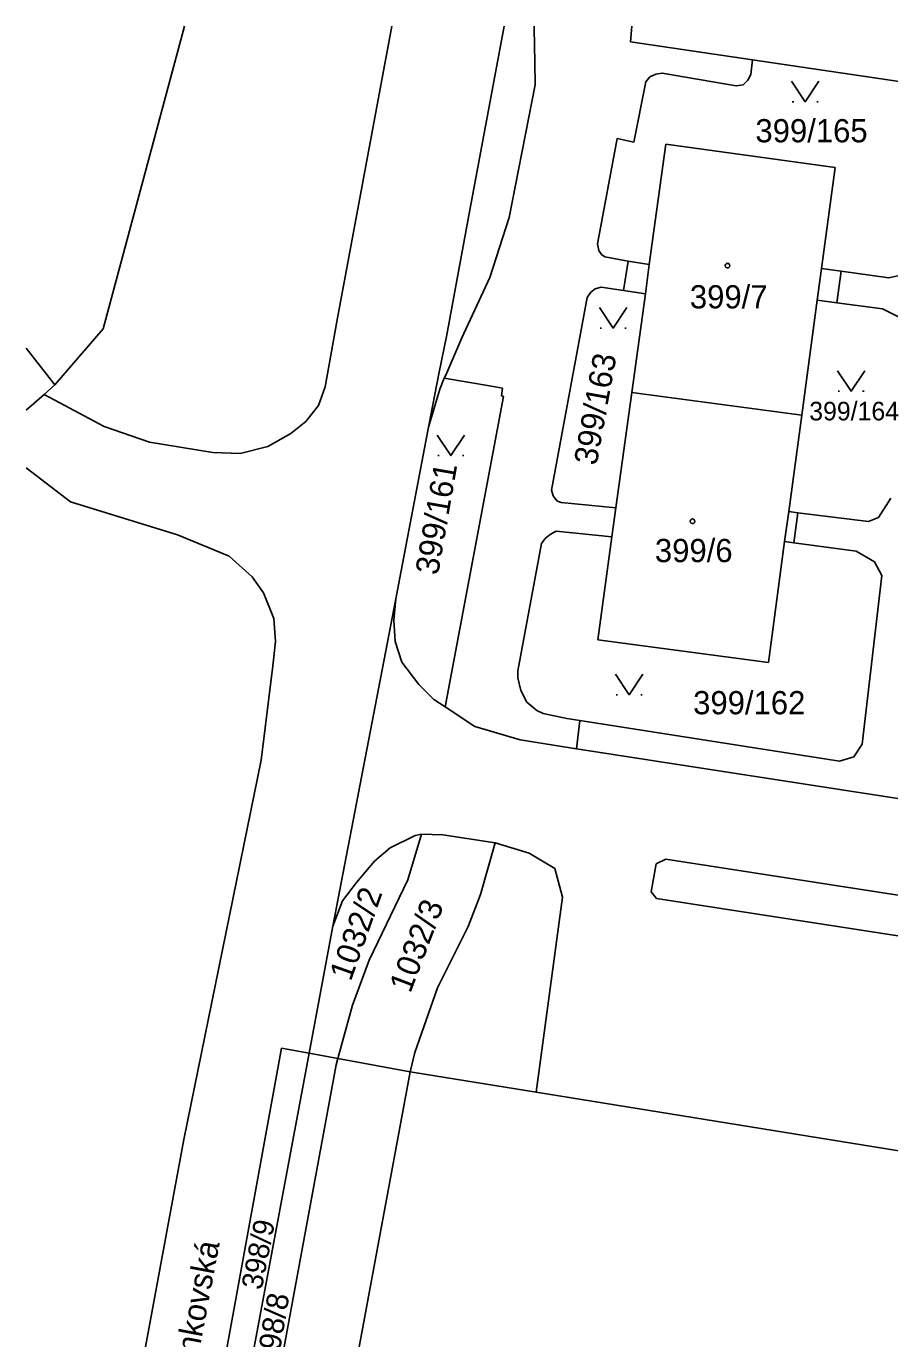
# Model space of a CAD drawing. Extents: x -851495 to -851222, y -1010479 to -1010202.
# Drawn here: x -851494.8 to -851431.6, y -1010299.4 to -1010203.3 of the extents above; entities that cross this region are included whole.
import ezdxf

# ---------------------------------------------------------------- set-up
doc = ezdxf.new("R2010")
doc.units = 0
for name, color, linetype in [('1', 7, 'Continuous'), ('12', 7, 'Continuous'), ('2', 7, 'Continuous'), ('3', 7, 'Continuous'), ('4', 7, 'Continuous'), ('5', 7, 'Continuous'), ('7', 7, 'Continuous')]:
    doc.layers.add(name, color=color, linetype=linetype)

# ---------------------------------------------------------------- blocks, each defined once
blk = doc.blocks.new('314')
for p, q in [((-0.95, 0), (-0.85, 0)), ((0.85, 0), (0.95, 0))]:
    blk.add_line(p, q)
blk.add_lwpolyline([(-1, 1.5), (0, 0), (1, 1.5)])
blk = doc.blocks.new('404')
blk.add_lwpolyline([(0, 0.17), (0.1, 0.15), (0.15, 0.06), (0.17, 0), (0.15, -0.09), (0.07, -0.16), (0, -0.17), (-0.09, -0.14), (-0.15, -0.08), (-0.17, 0), (-0.15, 0.09), (-0.07, 0.16), (0, 0.17)])

msp = doc.modelspace()

# ---------------------------------------------------------------- linework, layer by layer
at = {"layer": '1'}
for p, q in [((-851489.19, -1010225.42), (-851483.22, -1010203.26)), ((-851457.63, -1010203.26), (-851457.62, -1010203.43)), ((-851457.62, -1010203.43), (-851457.56, -1010205.89)), ((-851450.57, -1010204.41), (-851450.46, -1010203.26)), ((-851450.57, -1010204.41), (-851441.63, -1010205.73)), ((-851441.76, -1010206.79), (-851441.63, -1010205.73)), ((-851441.63, -1010205.73), (-851427.84, -1010207.75)), ((-851457.56, -1010205.89), (-851457.54, -1010207.55)), ((-851448.71, -1010206.76), (-851448.24, -1010206.7)), ((-851448.24, -1010206.7), (-851442.84, -1010207.63)), ((-851457.54, -1010207.55), (-851459.44, -1010217.27)), ((-851450.32, -1010211.75), (-851449.44, -1010207.33)), ((-851449.44, -1010207.33), (-851449.15, -1010206.97)), ((-851449.15, -1010206.97), (-851448.71, -1010206.76)), ((-851442.84, -1010207.63), (-851442.31, -1010207.55)), ((-851442.31, -1010207.55), (-851441.98, -1010207.22)), ((-851441.98, -1010207.22), (-851441.76, -1010206.79)), ((-851452.99, -1010219.19), (-851451.54, -1010211.49)), ((-851451.54, -1010211.49), (-851450.32, -1010211.75)), ((-851447.97, -1010211.89), (-851449.19, -1010220.71)), ((-851435.58, -1010213.6), (-851447.97, -1010211.89)), ((-851436.57, -1010221), (-851435.58, -1010213.6)), ((-851459.44, -1010217.27), (-851460.87, -1010221.65)), ((-851452.88, -1010219.67), (-851452.99, -1010219.19)), ((-851452.68, -1010219.97), (-851452.88, -1010219.67)), ((-851452.45, -1010220.15), (-851452.68, -1010219.97)), ((-851452.45, -1010220.15), (-851450.73, -1010220.45)), ((-851450.73, -1010220.45), (-851451.07, -1010222.6)), ((-851450.73, -1010220.45), (-851449.19, -1010220.71)), ((-851435.15, -1010221.2), (-851436.57, -1010221)), ((-851460.87, -1010221.65), (-851462.92, -1010226.07)), ((-851435.47, -1010223.51), (-851435.15, -1010221.2)), ((-851435.15, -1010221.2), (-851431.65, -1010221.67)), ((-851431.65, -1010221.67), (-851430.11, -1010221.35)), ((-851453.73, -1010223.13), (-851453.46, -1010222.72)), ((-851453.46, -1010222.72), (-851453.16, -1010222.48)), ((-851453.16, -1010222.48), (-851452.71, -1010222.36)), ((-851452.71, -1010222.36), (-851451.07, -1010222.6)), ((-851451.07, -1010222.6), (-851449.48, -1010222.86)), ((-851450.47, -1010230.07), (-851449.48, -1010222.86)), ((-851456.36, -1010237.22), (-851453.73, -1010223.13)), ((-851436.89, -1010223.32), (-851438.03, -1010231.74)), ((-851435.47, -1010223.51), (-851436.89, -1010223.32)), ((-851432.12, -1010223.96), (-851435.47, -1010223.51)), ((-851430.8, -1010224.61), (-851432.12, -1010223.96)), ((-851492.72, -1010229.51), (-851489.19, -1010225.42)), ((-851492.72, -1010229.51), (-851494.81, -1010226.82)), ((-851462.92, -1010226.07), (-851464.1, -1010228.8)), ((-851464.1, -1010228.8), (-851464.2, -1010229.02)), ((-851493.51, -1010230.22), (-851492.72, -1010229.51)), ((-851464.2, -1010229.02), (-851464.52, -1010229.84)), ((-851464.2, -1010229.02), (-851460.75, -1010229.61)), ((-851460.75, -1010229.61), (-851459.94, -1010229.75)), ((-851459.94, -1010229.75), (-851460.01, -1010230.32)), ((-851494.81, -1010231.37), (-851493.51, -1010230.22)), ((-851464.52, -1010229.84), (-851465.35, -1010232.61)), ((-851459.87, -1010230.36), (-851460.62, -1010234.41)), ((-851460.01, -1010230.32), (-851459.87, -1010230.36)), ((-851451.64, -1010238.53), (-851450.47, -1010230.07)), ((-851438.03, -1010231.74), (-851450.47, -1010230.07)), ((-851467.76, -1010245.18), (-851465.35, -1010232.61)), ((-851438.03, -1010231.74), (-851438.98, -1010238.79)), ((-851460.62, -1010234.41), (-851464.13, -1010253.1)), ((-851456.22, -1010237.65), (-851456.36, -1010237.22)), ((-851455.96, -1010238.02), (-851456.22, -1010237.65)), ((-851455.64, -1010238.14), (-851455.96, -1010238.02)), ((-851455.64, -1010238.14), (-851451.64, -1010238.53)), ((-851432.4, -1010239.22), (-851431.5, -1010237.81)), ((-851451.64, -1010238.53), (-851451.93, -1010240.64)), ((-851438.31, -1010238.88), (-851438.98, -1010238.79)), ((-851438.62, -1010241.08), (-851438.31, -1010238.88)), ((-851438.31, -1010238.88), (-851433.14, -1010239.53)), ((-851433.14, -1010239.53), (-851432.4, -1010239.22)), ((-851456.45, -1010240.47), (-851456.02, -1010240.22)), ((-851451.93, -1010240.64), (-851456.02, -1010240.22)), ((-851458.82, -1010250.47), (-851457.09, -1010241.14)), ((-851457.09, -1010241.14), (-851456.81, -1010240.77)), ((-851456.81, -1010240.77), (-851456.45, -1010240.47)), ((-851451.93, -1010240.64), (-851452.97, -1010248.19)), ((-851440.47, -1010249.84), (-851439.28, -1010241)), ((-851438.62, -1010241.08), (-851439.28, -1010241)), ((-851434.05, -1010241.7), (-851438.62, -1010241.08)), ((-851432.7, -1010242.48), (-851434.05, -1010241.7)), ((-851432.16, -1010243.47), (-851432.7, -1010242.48)), ((-851433.6, -1010255.82), (-851432.16, -1010243.47)), ((-851467.76, -1010245.18), (-851472.37, -1010269.15)), ((-851467.76, -1010245.18), (-851467.89, -1010246.74)), ((-851467.89, -1010246.74), (-851467.81, -1010248.3)), ((-851467.81, -1010248.3), (-851467.31, -1010249.82)), ((-851452.97, -1010248.19), (-851440.47, -1010249.84)), ((-851467.31, -1010249.82), (-851466.07, -1010251.45)), ((-851458.82, -1010250.97), (-851458.82, -1010250.47)), ((-851466.07, -1010251.45), (-851464.96, -1010252.55)), ((-851458.6, -1010251.9), (-851458.82, -1010250.97)), ((-851458.15, -1010252.76), (-851458.6, -1010251.9)), ((-851464.13, -1010253.1), (-851464.96, -1010252.55)), ((-851457.42, -1010253.37), (-851458.15, -1010252.76)), ((-851461.97, -1010254.53), (-851464.13, -1010253.1)), ((-851456.95, -1010253.58), (-851457.42, -1010253.37)), ((-851455.24, -1010253.94), (-851456.95, -1010253.58)), ((-851458.64, -1010255.52), (-851461.97, -1010254.53)), ((-851455.24, -1010253.94), (-851454.28, -1010254.09)), ((-851454.53, -1010256.16), (-851454.28, -1010254.09)), ((-851454.28, -1010254.09), (-851435.27, -1010257.08)), ((-851454.53, -1010256.16), (-851458.64, -1010255.52)), ((-851428.27, -1010260.23), (-851454.53, -1010256.16)), ((-851434.21, -1010256.75), (-851433.6, -1010255.82)), ((-851435.27, -1010257.08), (-851434.21, -1010256.75)), ((-851466.86, -1010265.76), (-851465.87, -1010262.43)), ((-851466.33, -1010262.51), (-851465.87, -1010262.43)), ((-851465.87, -1010262.43), (-851464.32, -1010262.46)), ((-851464.32, -1010262.46), (-851460.48, -1010263.06)), ((-851469.3, -1010264.39), (-851468.17, -1010263.42)), ((-851468.17, -1010263.42), (-851466.33, -1010262.51)), ((-851460.48, -1010263.06), (-851461.55, -1010266.83)), ((-851470.62, -1010265.96), (-851469.3, -1010264.39)), ((-851471.65, -1010267.31), (-851470.62, -1010265.96)), ((-851469.69, -1010271.64), (-851466.86, -1010265.76)), ((-851461.55, -1010266.83), (-851462.45, -1010269.19)), ((-851472.37, -1010269.15), (-851471.65, -1010267.31)), ((-851472.37, -1010269.15), (-851474.1, -1010278.46)), ((-851462.45, -1010269.19), (-851464.7, -1010273.68)), ((-851470.92, -1010274.93), (-851469.69, -1010271.64)), ((-851464.7, -1010273.68), (-851466.35, -1010278.41)), ((-851471.99, -1010278.84), (-851470.92, -1010274.93)), ((-851476.12, -1010278.09), (-851482.49, -1010313.06)), ((-851478.85, -1010303.92), (-851474.1, -1010278.46)), ((-851476.12, -1010278.09), (-851474.1, -1010278.46)), ((-851474.1, -1010278.46), (-851471.99, -1010278.84)), ((-851466.35, -1010278.41), (-851466.71, -1010279.81)), ((-851472.11, -1010279.3), (-851479.01, -1010316.73)), ((-851471.99, -1010278.84), (-851472.11, -1010279.3)), ((-851471.99, -1010278.84), (-851466.71, -1010279.81)), ((-851473.7, -1010317.66), (-851466.71, -1010279.81)), ((-851466.71, -1010279.81), (-851465.64, -1010280)), ((-851465.64, -1010280), (-851457.47, -1010281.32)), ((-851457.47, -1010281.32), (-851386.12, -1010292.85))]:
    msp.add_line(p, q, dxfattribs=at)
at = {"layer": '12'}
for p, q in [((-851447.97, -1010211.89), (-851449.19, -1010220.71)), ((-851435.58, -1010213.6), (-851447.97, -1010211.89)), ((-851436.57, -1010221), (-851435.58, -1010213.6)), ((-851449.19, -1010220.71), (-851449.48, -1010222.86)), ((-851436.57, -1010221), (-851436.89, -1010223.32)), ((-851450.47, -1010230.07), (-851449.48, -1010222.86)), ((-851436.89, -1010223.32), (-851438.03, -1010231.74)), ((-851451.64, -1010238.53), (-851450.47, -1010230.07)), ((-851438.03, -1010231.74), (-851450.47, -1010230.07)), ((-851438.03, -1010231.74), (-851450.47, -1010230.07)), ((-851438.03, -1010231.74), (-851438.98, -1010238.79)), ((-851451.64, -1010238.53), (-851451.93, -1010240.64)), ((-851438.98, -1010238.79), (-851439.28, -1010241)), ((-851451.93, -1010240.64), (-851452.97, -1010248.19)), ((-851440.47, -1010249.84), (-851439.28, -1010241)), ((-851452.97, -1010248.19), (-851440.47, -1010249.84))]:
    msp.add_line(p, q, dxfattribs=at)
at = {"layer": '4'}
for p, q in [((-851468.05, -1010203.26), (-851472.04, -1010224.75)), ((-851462.44, -1010217.23), (-851459.81, -1010203.26)), ((-851462.44, -1010217.23), (-851464.01, -1010225.86)), ((-851449.19, -1010220.71), (-851449.48, -1010222.86)), ((-851436.57, -1010221), (-851436.89, -1010223.32)), ((-851472.04, -1010224.75), (-851472.92, -1010229.66)), ((-851472.92, -1010229.66), (-851473.4, -1010231.02)), ((-851489.11, -1010232.57), (-851493.51, -1010230.22)), ((-851473.4, -1010231.02), (-851474.35, -1010232.19)), ((-851485.78, -1010233.71), (-851489.11, -1010232.57)), ((-851474.35, -1010232.19), (-851475.44, -1010233.08)), ((-851475.44, -1010233.08), (-851477.13, -1010234.04)), ((-851481.14, -1010234.47), (-851485.78, -1010233.71)), ((-851479.14, -1010234.55), (-851481.14, -1010234.47)), ((-851477.13, -1010234.04), (-851479.14, -1010234.55)), ((-851494.81, -1010235.6), (-851491.58, -1010238.08)), ((-851491.58, -1010238.08), (-851483.73, -1010240.51)), ((-851438.98, -1010238.79), (-851439.28, -1010241)), ((-851483.73, -1010240.51), (-851479.96, -1010242.06)), ((-851479.96, -1010242.06), (-851478.27, -1010243.57)), ((-851478.27, -1010243.57), (-851477.43, -1010244.75)), ((-851477.43, -1010244.75), (-851476.69, -1010246.63)), ((-851476.69, -1010246.63), (-851476.55, -1010248.3)), ((-851476.55, -1010248.3), (-851476.75, -1010250.1)), ((-851476.75, -1010250.1), (-851477.62, -1010256.99)), ((-851477.62, -1010256.99), (-851483.26, -1010284.78)), ((-851457.99, -1010263.81), (-851460.48, -1010263.06)), ((-851456.1, -1010264.94), (-851457.99, -1010263.81)), ((-851448.68, -1010264.58), (-851447.98, -1010264.26)), ((-851447.98, -1010264.26), (-851428.1, -1010267.33)), ((-851455.55, -1010267.02), (-851456.1, -1010264.94)), ((-851449.05, -1010266.63), (-851448.68, -1010264.58)), ((-851457.47, -1010281.32), (-851455.55, -1010267.02)), ((-851448.67, -1010267.14), (-851449.05, -1010266.63)), ((-851427.72, -1010270.37), (-851448.67, -1010267.14)), ((-851483.26, -1010284.78), (-851489.25, -1010316.96))]:
    msp.add_line(p, q, dxfattribs=at)
msp.add_lwpolyline([(-851465.35, -1010232.61), (-851464.6, -1010228.71), (-851464.01, -1010225.86)], dxfattribs=at)

# ---------------------------------------------------------------- block references
at = {"layer": '3'}
for p in [(-851437.77, -1010208.79), (-851451.83, -1010225.36), (-851434.42, -1010229.99), (-851463.72, -1010234.7), (-851450.67, -1010252.21)]:
    msp.add_blockref('314', p, dxfattribs=at)
at = {"layer": '5'}
for p in [(-851443.47, -1010220.79), (-851446.03, -1010239.51)]:
    msp.add_blockref('404', p, dxfattribs=at)

# ---------------------------------------------------------------- texts
at = {"layer": '2'}
for s, height, p in [('399/165', 1.7, (-851441.42, -1010211.76)), ('399/7', 1.7, (-851446.22, -1010223.92)), ('399/164', 1.36, (-851437.48, -1010232.12)), ('399/6', 1.7, (-851448.78, -1010242.5)), ('399/162', 1.7, (-851445.98, -1010253.64))]:
    msp.add_text(s, height=height, dxfattribs=at).set_placement(p)
for s, height, rotation, p in [('399/163', 1.7, 79.698, (-851453.05, -1010235.47)), ('399/161', 1.7, 80.099, (-851464.66, -1010243.5)), ('1032/2', 1.7, 70.302, (-851471.05, -1010273.25)), ('1032/3', 1.7, 69.156, (-851466.69, -1010274.12)), ('398/9', 1.53, 78.954, (-851477.57, -1010295.84)), ('398/8', 1.6, 80.501, (-851476.42, -1010301.45))]:
    msp.add_text(s, height=height, rotation=rotation, dxfattribs=at).set_placement(p)
at = {"layer": '7'}
msp.add_text('Čankovská', height=1.7, rotation=79.297, dxfattribs=at).set_placement((-851482.73, -1010303.41))

doc.saveas('drawing.dxf')
